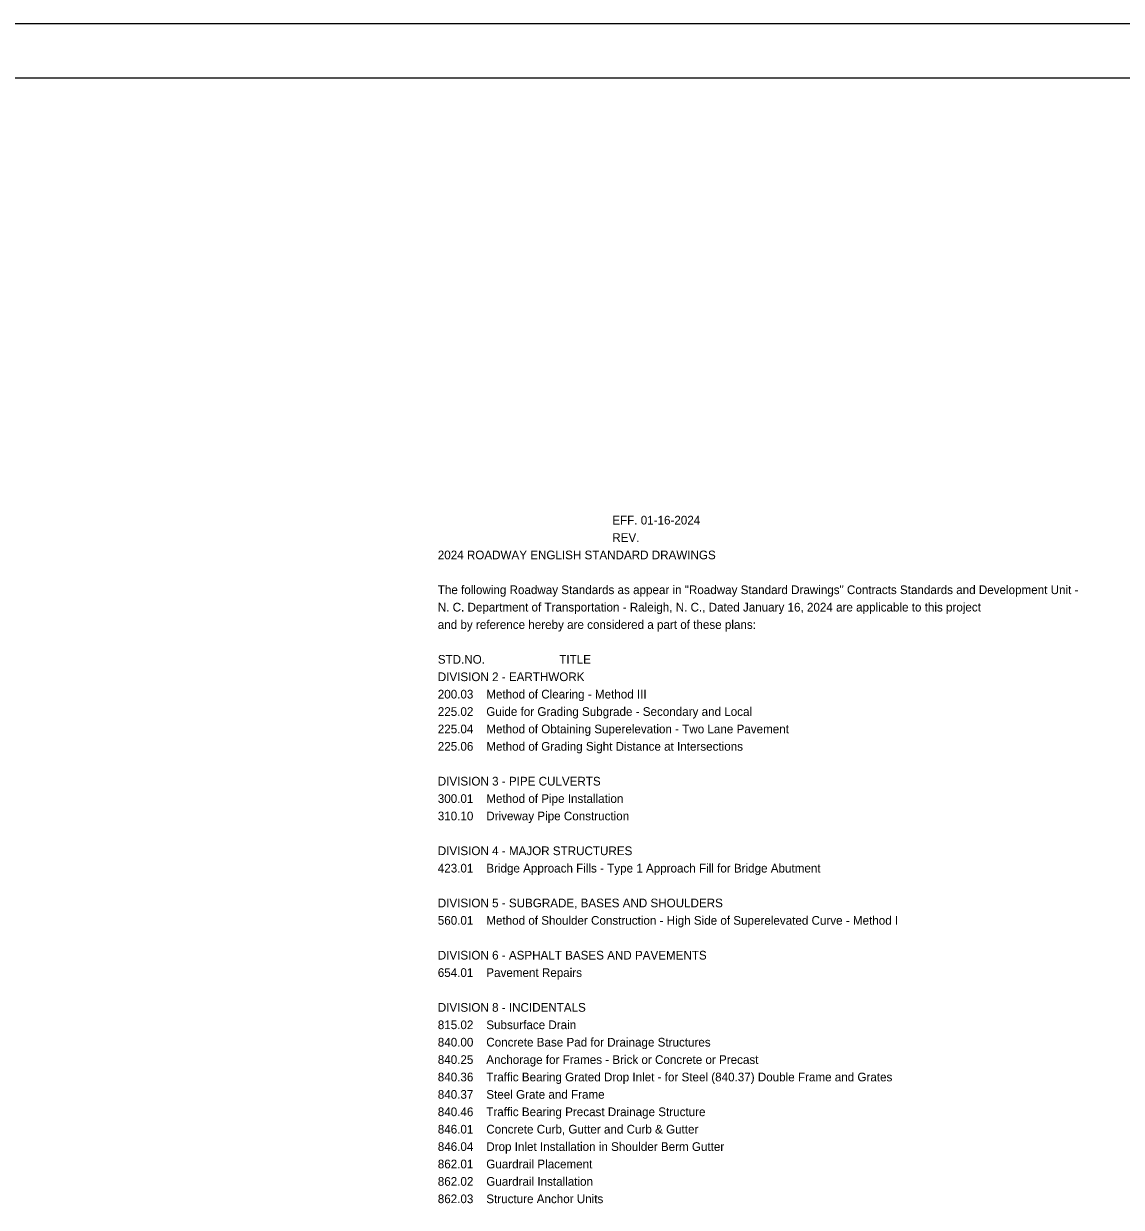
# Model space of a CAD drawing. Extents: x 885343.6 to 885383.5, y 651350.8 to 651372.8.
# Drawn here: x 885353.69 to 885363.79, y 651361.88 to 651372.76 of the extents above; entities that cross this region are included whole.
import ezdxf

# ---------------------------------------------------------------- set-up
doc = ezdxf.new("R2010")
doc.units = 0
for name, color, linetype in [('Sheet Data Text CELL', 7, 'Continuous'), ('Sheet Plan CELL', 7, 'Continuous'), ('Stewart Plot Border Xerox6279 and LJ5000', 7, 'Continuous')]:
    doc.layers.add(name, color=color, linetype=linetype)

msp = doc.modelspace()

# ---------------------------------------------------------------- linework, layer by layer
at = {"layer": 'Sheet Plan CELL'}
msp.add_lwpolyline([(885377.098, 651372.262), (885347.098, 651372.262), (885347.098, 651351.262), (885377.098, 651351.262)], close=True, dxfattribs=at)
at = {"layer": 'Stewart Plot Border Xerox6279 and LJ5000'}
msp.add_lwpolyline([(885343.598, 651372.762), (885377.598, 651372.762), (885377.598, 651350.762), (885343.598, 651350.762)], close=True, dxfattribs=at)

# ---------------------------------------------------------------- texts
at = {"layer": 'Sheet Data Text CELL'}
for s, p in [('                                                      EFF. 01-16-2024', (885357.501, 651368.157)), ('                                                      REV. ', (885357.501, 651367.997)), ('2024 ROADWAY ENGLISH STANDARD DRAWINGS', (885357.501, 651367.837)), ('The following Roadway Standards as appear in "Roadway Standard Drawings" Contracts Standards and Development Unit -', (885357.501, 651367.517)), ('N. C. Department of Transportation - Raleigh, N. C., Dated January 16, 2024 are applicable to this project', (885357.501, 651367.357)), ('and by reference hereby are considered a part of these plans:', (885357.501, 651367.197)), ('STD.NO.                       TITLE', (885357.501, 651366.877)), ('DIVISION 2 - EARTHWORK', (885357.501, 651366.717)), ('200.03    Method of Clearing - Method III', (885357.501, 651366.557)), ('225.02    Guide for Grading Subgrade - Secondary and Local', (885357.501, 651366.397)), ('225.04    Method of Obtaining Superelevation - Two Lane Pavement', (885357.501, 651366.237)), ('225.06    Method of Grading Sight Distance at Intersections', (885357.501, 651366.077)), ('DIVISION 3 - PIPE CULVERTS', (885357.501, 651365.757)), ('300.01    Method of Pipe Installation ', (885357.501, 651365.597)), ('310.10    Driveway Pipe Construction', (885357.501, 651365.437)), ('DIVISION 4 - MAJOR STRUCTURES', (885357.501, 651365.117)), ('423.01    Bridge Approach Fills - Type 1 Approach Fill for Bridge Abutment', (885357.501, 651364.957)), ('DIVISION 5 - SUBGRADE, BASES AND SHOULDERS', (885357.501, 651364.637)), ('560.01    Method of Shoulder Construction - High Side of Superelevated Curve - Method I', (885357.501, 651364.477)), ('DIVISION 6 - ASPHALT BASES AND PAVEMENTS', (885357.501, 651364.157)), ('654.01    Pavement Repairs', (885357.501, 651363.997)), ('DIVISION 8 - INCIDENTALS', (885357.501, 651363.677)), ('815.02    Subsurface Drain', (885357.501, 651363.517)), ('840.00    Concrete Base Pad for Drainage Structures', (885357.501, 651363.357)), ('840.25    Anchorage for Frames - Brick or Concrete or Precast', (885357.501, 651363.197)), ('840.36    Traffic Bearing Grated Drop Inlet - for Steel (840.37) Double Frame and Grates', (885357.501, 651363.037)), ('840.37    Steel Grate and Frame', (885357.501, 651362.877)), ('840.46    Traffic Bearing Precast Drainage Structure', (885357.501, 651362.717)), ('846.01    Concrete Curb, Gutter and Curb & Gutter', (885357.501, 651362.557)), ('846.04    Drop Inlet Installation in Shoulder Berm Gutter', (885357.501, 651362.397)), ('862.01    Guardrail Placement', (885357.501, 651362.237)), ('862.02    Guardrail Installation', (885357.501, 651362.077)), ('862.03    Structure Anchor Units', (885357.501, 651361.917))]:
    msp.add_text(s, height=0.08, dxfattribs=at).set_placement(p)

doc.saveas('drawing.dxf')
